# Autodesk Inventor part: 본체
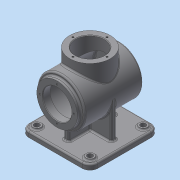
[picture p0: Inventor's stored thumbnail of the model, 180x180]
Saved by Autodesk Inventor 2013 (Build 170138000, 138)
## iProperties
Created: 2015-07
Part Number: 본체
Material: 일반
Document SubType Name: Modeling
Designer: dgall
Density: 1 g/cm^3
Author: dgall
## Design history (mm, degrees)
sketch "스케치1"
  geometry: L1 (-65, 65)-(65, 65); L2 (65, 65)-(65, -65); L3 (65, -65)-(-65, -65); L4 (-65, -65)-(-65, 65); 3 further points
  constraints: 8 end point, 2 midpoint, 2 parallel, 1 horizontal, 1 horizontal alignment, 1 perpendicular, 1 vertical alignment
  dimensions: "d0" = 130 distance of L1.start L1.end; "d2" = 130 distance of L3.end L1.start
extrude "돌출1" new body sketch "스케치1" distance "d3" = 10; taper "d4" = 0 deg
sketch "스케치2"
  geometry: L1 (65, 0)-(-65, 0) reference; L2 (65, -10)-(-65, -10) reference; C1 r 45 at (0, 68); 2 further points
  constraints: 1 centre point, 1 midpoint, 1 vertical alignment
  dimensions: "d5" = 90 diameter of C1; "d7" = 78 distance from line of L2 C1.centre
extrude "돌출2" join sketch "스케치2" stored distance "d8" = 110; taper "d9" = 0 deg
sketch "스케치3"
  geometry: C1 r 45 at (0, 0) reference; C2 r 38 at (0, 0); 1 further point
  constraints: 1 centre point, 1 coincident
  dimensions: "d10" = 76 diameter of C2
extrude "돌출3" join sketch "스케치3" distance "d12" = 7; taper "d13" = 0 deg
sketch "스케치4"
  geometry: L1 (-65, 65)-(65, 65) reference; L2 (-65, -65)-(-65, 65) reference; C1 r 7.5 at (-50, 50); 1 further point
  constraints: 1 centre point
  dimensions: "d14" = 15 diameter of C1; "d17" = 15 distance from line of L2 C1.centre; "d18" = 15 distance from line of L1 C1.centre (= d17)
extrude "돌출4" join sketch "스케치4" distance "d19" = 3; taper "d20" = 0 deg
node "작업 평면1"
sketch "스케치5"
  geometry: C1 r 38 at (0, 0); 1 further point
  constraints: 1 centre point, 1 coincident
  dimensions: "d28" = 76 diameter of C1
extrude "돌출5" join sketch "스케치5" stored distance "d30" = 20; taper "d31" = 0 deg
sketch "스케치6"
  geometry: L1 (-5, 45)-(5, 45); L2 (5, -45)-(-5, -45); L3 (45, 5)-(45, -5); L4 (-45, -5)-(-45, 5); L5 (5, 45)-(5, 5); L6 (5, -5)-(5, -45); L7 (-5, -45)-(-5, -5); L8 (-5, 5)-(-5, 45); L9 (45, -5)-(5, -5); L10 (-5, -5)-(-45, -5); L11 (-45, 5)-(-5, 5); L12 (5, 5)-(45, 5); 5 further points
  constraints: 24 end point, 10 parallel, 4 horizontal alignment, 4 perpendicular, 4 vertical alignment, 3 horizontal, 2 midpoint
  dimensions: "d32" = 90 distance of L1.end L2.start; "d34" = 90 distance of L4.end L3.start; "d35" = 10 distance of L1.start L1.end; "d36" = 10 distance of L3.start L3.end; "d37" = 45 distance of point (-45, 0) point (0, 0); "d38" = 45 distance of point (0, 0) point (0, 45)
extrude "돌출6" join sketch "스케치6" stored distance "d39" = 20; taper "d40" = 0 deg
hole "구멍1" diameter "d43" = 54; stored, may be unused: countersink angle "d47" = 90 deg, drill point angle "d49" = 0 deg; dims "d41" = 10, "d42" = 10, "d44" = 6, "d45" = 4, "d46" = 2, "d48" = 14
hole "구멍2" diameter "d52" = 80; stored, may be unused: countersink angle "d56" = 90 deg, drill point angle "d58" = 0 deg; dims "d50" = 10, "d51" = 10, "d53" = 6, "d54" = 4, "d55" = 2, "d57" = 96
hole "구멍3" diameter "d61" = 54; stored, may be unused: countersink angle "d65" = 90 deg, drill point angle "d67" = 0 deg; dims "d59" = 10, "d60" = 10, "d62" = 6, "d63" = 4, "d64" = 2, "d66" = 96
sketch "스케치7"
  geometry: C1 r 27 at (0, 0) reference; 1 further point
  constraints: 1 vertical alignment
  dimensions: "d68" = 32 distance of point (0, 32) C1.centre
hole "구멍4" sketch "스케치7" at (0, 32) diameter "d69" = 3.242; stored, may be unused: countersink angle "d73" = 90 deg, drill point angle "d75" = 118 deg; dims "d70" = 8, "d71" = 4, "d72" = 2, "d74" = 10
sketch "스케치8"
  geometry: C1 r 27 at (0, 0) reference; 2 further points
  constraints: 1 vertical alignment
  dimensions: "d79" = 32 distance of point (0, 32) C1.centre
hole "구멍5" sketch "스케치8" at (0, 32) diameter "d80" = 3.242; stored, may be unused: countersink angle "d84" = 90 deg, drill point angle "d86" = 118 deg; dims "d81" = 8, "d82" = 4, "d83" = 2, "d85" = 10
sketch "스케치9"
  geometry: C1 r 45 at (0, 0) reference; 2 further points
  constraints: 1 coincident, 1 other
feature "엠보싱1" sketch "스케치9" dims "d0" = 130, "d2" = 130, "d12" = 7, "d90" = 0.5, "d91" = 0
hole "구멍6" diameter "d94" = 10; stored, may be unused: countersink angle "d98" = 90 deg, drill point angle "d100" = 118 deg; dims "d92" = 10, "d93" = 10, "d95" = 8, "d96" = 4, "d97" = 2, "d99" = 10
fillet "모깎기1" dims "d107" = 3
chamfer "모따기1" distance "d114" = 1; stored, may be unused: second distance "d115" = 2, angle "d116" = 45 deg
fillet "모깎기2" dims "d117" = 3
fillet "모깎기3" dims "d118" = 3
fillet "모깎기4" dims "d119" = 3
fillet "모깎기5" dims "d120" = 3
fillet "모깎기6" dims "d121" = 15
fillet "모깎기7" dims "d122" = 3
node "솔리드1"
pattern_linear "직사각형 패턴1" dims "d23" = 100
pattern_circular "원형 패턴1" dims angle "d77" = 360 deg
pattern_circular "원형 패턴2" dims angle "d88" = 360 deg
pattern_linear "직사각형 패턴2" dims "d103" = 100
pattern_linear "직사각형 패턴3" dims "d110" = 100
